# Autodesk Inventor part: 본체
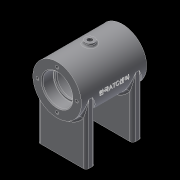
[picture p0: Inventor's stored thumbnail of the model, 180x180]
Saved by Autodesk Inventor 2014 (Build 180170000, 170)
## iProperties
Created: 2020-07
Part Number: 본체
Material: Generic
Document SubType Name: Modeling
Designer: kh
Density: 1 g/cm^3
Appearance: Default
Author: kh
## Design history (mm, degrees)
sketch "Sketch1"
  geometry: C1 r 26 at (0, 0); 1 further point
  constraints: 1 centre point, 1 coincident
  dimensions: "d0" = 52 diameter of C1
extrude "Extrusion1" new body sketch "Sketch1" stored distance "d1" = 70; taper "d2" = 0 deg
workplane "Work Plane1"
sketch "Sketch2"
  geometry: L1 (-26, 0)-(26, 0); L2 (26, 0)-(26, -64); L3 (26, -64)-(-26, -64); L4 (-26, -64)-(-26, 0); 2 further points
  constraints: 8 end point, 2 coincident, 2 parallel, 1 horizontal, 1 midpoint, 1 perpendicular
  dimensions: "d4" = 52 distance of L2.end L3.end; "d5" = 64 distance of L1.end L2.end
extrude "Extrusion2" join sketch "Sketch2" distance "d6" = 10; taper "d7" = 0 deg
mirror "Mirror1"
sketch "Sketch3"
  geometry: L1 (0, 0)-(0, -74.645); L2 (0, 0)-(8.893, -24.432); L3 (8.893, -24.432)-(9.919, -27.251); L4 (6.851, -18.824)-(1.213, -20.876); L5 (1.213, -20.876)-(4.28, -29.303); L6 (4.28, -29.303)-(9.919, -27.251); L7 (9.919, -27.251)-(6.851, -18.824); A1 r 26 centre (0, 0) between (-26, 0) and (26, 0) reference
  constraints: 15 end point, 2 parallel, 2 perpendicular, 1 collinear, 1 point on circle, 1 point on line, 1 vertical
  dimensions: "d8" = 20 deg angle of L2 L1; "d12" = 6 distance between parallel lines of L2 L5; "d83" = 29 distance from line of L1.start L6
revolve "Revolution1" sketch "Sketch3" stored, may be unused: angle "d13" = 90 deg
workplane "Work Plane3"
sketch "Sketch5"
  geometry: C1 r 5 at (0, 0); 1 further point
  constraints: 1 centre point, 1 coincident
  dimensions: "d15" = 10 diameter of C1
extrude "Extrusion3" join sketch "Sketch5" distance "d16" = 10; taper "d17" = 0 deg
sketch "Sketch6"
  geometry: L1 (0, 35)-(16, 35); L2 (16, 35)-(16, 23); L3 (16, 23)-(14, 23); L4 (14, 23)-(14, 21); L5 (14, 21)-(21, 21); L6 (21, 21)-(21, -21); L7 (21, -21)-(14, -21); L8 (14, -21)-(14, -23); L9 (14, -23)-(16, -23); L10 (16, -23)-(16, -35); L11 (16, -35)-(0, -35); L12 (0, -35)-(0, 35); L13 (26, 35)-(-26, 35) reference; L14 (-26, -35)-(26, -35) reference; 1 further point
  constraints: 24 end point, 9 parallel, 2 collinear, 1 horizontal, 1 midpoint, 1 perpendicular
  dimensions: "d18" = 28 diameter of L4 L12; "d19" = 12 distance of L1.end L2.end; "d20" = 42 distance of L5.end L6.end; "d21" = 12 distance of L9.end L10.end; "d22" = 2 distance of L7.end L8.end; "d23" = 2 distance of L3.end L4.end; "d24" = 32 diameter of L2 L12; "d25" = 42 diameter of L6 L12; "d26" = 32 diameter of L10 L12; "d27" = 28 diameter of L8 L12
revolve "Revolution2" sketch "Sketch6" stored, may be unused: angle "d28" = 90 deg
sketch "Sketch7"
  geometry: C1 r 16 at (0, 0) reference; 1 further point
  constraints: 1 vertical alignment
  dimensions: "d29" = 21 distance of point (0, 21) C1.centre
hole "Hole1" sketch "Sketch7" at (0, 21) diameter "d30" = 3.242; stored, may be unused: countersink angle "d34" = 90 deg, drill point angle "d36" = 118 deg; dims "d31" = 8, "d32" = 4, "d33" = 2, "d35" = 10
pattern_circular "Circular Pattern1" dims angle "d38" = 360 deg
mirror "Mirror2"
hole "Hole2" diameter "d42" = 5.188; stored, may be unused: countersink angle "d46" = 90 deg, drill point angle "d48" = 118 deg; dims "d40" = 10, "d41" = 10, "d43" = 8, "d44" = 4, "d45" = 2, "d47" = 10
hole "Hole3" diameter "d51" = 5.188; stored, may be unused: countersink angle "d55" = 90 deg, drill point angle "d57" = 118 deg; dims "d49" = 10, "d50" = 10, "d52" = 8, "d53" = 4, "d54" = 2, "d56" = 10
sketch "Sketch8"
  geometry: L1 (0, 10)-(52, 10) reference; 3 further points
  dimensions: "d58" = 40 distance of point (6, 5) point (46, 5); "d59" = 20 horizontal distance of point (26, -20) point (46, 5); "d60" = 5 distance from line of point (6, 5) L1
hole "Hole4" sketch "Sketch8" at (46, 5), (6, 5) diameter "d61" = 4.134; stored, may be unused: countersink angle "d65" = 90 deg, drill point angle "d67" = 118 deg; dims "d62" = 8, "d63" = 4, "d64" = 2, "d66" = 10
mirror "Mirror3"
workplane "Work Plane6"
sketch "Sketch9"
  geometry: L1 (-26, -35)-(26, -35) reference; L2 (-26, -35)-(-26, 35) reference; 2 further points
  constraints: 1 other
  dimensions: "d70" = 35 distance from line of point (0, 0) L1; "d71" = 26 distance from line of point (0, 0) L2
emboss "Emboss1" sketch "Sketch9" dims "d8" = 20 deg, "d12" = 6, "d72" = 0.5, "d73" = 0, "d83" = 29
fillet "Fillet1" dims "d74" = 2
fillet "Fillet2" dims "d75" = 0.3
fillet "Fillet3" dims "d76" = 3
chamfer "Chamfer1" distance "d77" = 1; stored, may be unused: second distance "d78" = 2, angle "d79" = 45 deg
fillet "Fillet4" dims "d80" = 3
fillet "Fillet5" dims "d81" = 3
fillet "Fillet6" dims "d82" = 3
body "Solid1"
other parameters: "d14" = 29, "d69" = -26.5
